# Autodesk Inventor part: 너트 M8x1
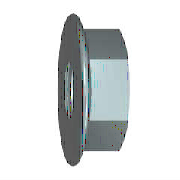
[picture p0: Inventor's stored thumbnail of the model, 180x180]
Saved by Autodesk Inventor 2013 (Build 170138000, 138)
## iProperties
Created: 2015-12
Part Number: 너트 M8x1
Material: 스테인리스강
Description: 플랜지붙이 6각 너트 - 일반 스레드
Document SubType Name: Modeling
Standard: ISO 4161
Designer: mdu
Standard Revision: 2판 1999-03-15
Standards Organization: ISO
Language: ko-KR
Size Designation: M8
Categories: <MemberInstance><Categories><Category DisplayName="조임쇠" InternalName="e4da775c-781d-43d5-af7c-5136215cf5a6" Mnemonic="FSTN"><Category DisplayName="너트" InternalN
Density: 8.08 g/cm^3
Author: mdu
IsCustomPart: 1
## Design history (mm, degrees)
sketch "스케치1"
  geometry: L1 (-1.844, 0)-(9.641, 0) reference; L2 (3.107, 6.5)-(2.288, 8.257); L3 (3.107, 6.5)-(8, 6.5); L4 (8, 6.5)-(8, 0); L5 (3.107, 6.5)-(3.107, 0); L6 (0, -1.835)-(0, 11.01) reference; A1 r 1.2 centre (1.2, 7.75) between (2.288, 8.257) and (0, 7.75); 1 further point
  constraints: 8 end point, 3 point on line, 2 perpendicular, 2 point on circle, 2 tangent, 1 centre point, 1 parallel
  dimensions: "d2" = 13 diameter of L3 L1 (= SW); "d4" = 17.9 dimension on A1 L1 (= LADI); "d5" = 1.2 radius of A1 (= PHH); "d15" = 8 distance between parallel lines of L4 L6 (= KOH); "d16" = 25 deg angle of L6 L2 (= KEWI)
revolve "링" sketch "스케치1" stored, may be unused: angle "d8" = 90 deg
sketch "스케치2"
  geometry: L1 (-6.5, -3.753)-(-6.5, 3.753); L2 (-6.5, 3.753)-(0, 7.506); L3 (0, 7.506)-(6.5, 3.753); L4 (6.5, 3.753)-(6.5, -3.753); L5 (6.5, -3.753)-(0, -7.506); L6 (0, -7.506)-(-6.5, -3.753); C1 r 4.9 at (0, 0); C2 r 7.75 at (0, 0) reference; 1 further point
  constraints: 12 end point, 1 centre point, 1 coincident, 1 vertical, 11 other
  dimensions: "d6" = 15.01111 distance of L5.end L2.end (= 1.1547 x SW)
extrude "본체" join sketch "스케치2" distance "d7" = 8 (= KOH); taper "d9" = 0 deg
sketch "스케치3"
  geometry: L1 (2.638, 7.506)-(8, 7.506) reference; L2 (8, 3.753)-(8, 7.506) reference; L3 (0, -7.75)-(0, 7.75) reference; L4 (-1.6, 0)-(9.6, 0) reference; L5 (7.419, 7.506)-(8, 6.5)
  constraints: 2 end point, 2 point on line
  dimensions: "d10" = 30 deg angle of L2 L5 (= ANG1); "d11" = 13 diameter of L5.end L4 (= SW0)
revolve "모따기1" sketch "스케치3" stored, may be unused: angle "d24" = 90 deg
sketch "스케치4"
  geometry: C1 r 7.75 at (0, 0) reference; 1 further point
  constraints: 1 coincident
hole "스레드" sketch "스케치4" at (0, 0) diameter "d25" = 6.917; stored, may be unused: countersink angle "d29" = 82 deg, drill point angle "d31" = 118 deg; dims "d26" = 6, "d27" = 4, "d28" = 2, "d30" = 8
workaxis "Work Axis1"
workplane "Work Plane1"
body "Solid1"
chamfer "모따기2" distance "d12" = 0.67658 (= -0.5 x GD1 + 0.5 x NND); stored, may be unused: angle "d13" = 30 deg, second distance "d46" = 0.67658 (= -0.5 x GD1 + 0.5 x NND)
chamfer "모따기3" distance "d51" = 0.67658 (= -0.5 x GD1 + 0.5 x NND); stored, may be unused: second distance "d52" = 2, angle "d53" = 45 deg
other parameters: "ANG1" = 30 deg [user parameter; used in 1 equation term], "KEWI" = 25 deg [user parameter; used in 1 equation term], "NND" = 8 [user parameter; used in 4 equation terms], "LADI" = 17.9 [user parameter; used in 2 equation terms], "SW" = 13 [user parameter; used in 3 equation terms], "PHH" = 1.2 [user parameter; used in 3 equation terms], "KOH" = 8 (= NND) [user parameter; used in 2 equation terms], "SW0" = 13 [user parameter; used in 1 equation term], "GD1" = 6.64684 (computed from THREADDIA, PTC, TOA) [user parameter; used in 3 equation terms], "d1" = 17.9 (= LADI), "d3" = 1.2 (= PHH), "d45" = 0, "d47" = 0, "d49" = 0, "d54" = 0, "GUL" = 0.67658 (= 0.541266 x PTC) [user parameter], "TPU" = 8 (computed from PTC) [user parameter], "RR" = 1.2 (= PHH) [user parameter], "THREADDIA" = 8 [user parameter; used in 1 equation term], "TOA" = 30 deg [user parameter; used in 1 equation term], "PTC" = 1.25 [user parameter; used in 4 equation terms], "GAL" = 0.67658 (= 0.541266 x PTC) [user parameter], "E0" = 15.015 (= 1.155 x SW) [user parameter]
